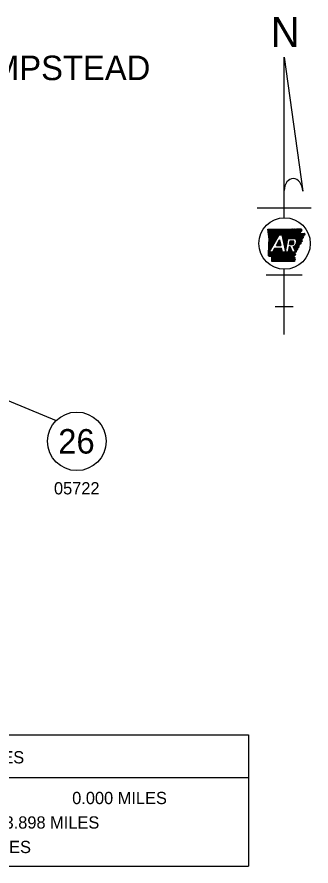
# Model space of a CAD drawing. Extents: x -12863 to 18921, y -8840 to 11152.
# Drawn here: x 4137 to 7017, y -8775 to -453 of the extents above; entities that cross this region are included whole.
import ezdxf

# ---------------------------------------------------------------- set-up
doc = ezdxf.new("R2010")
doc.units = 0
for name, color, linetype in [('Level 2', 7, 'Continuous'), ('Level 3', 7, 'Continuous'), ('Level 45', 7, 'Continuous'), ('Level 48', 7, 'Continuous'), ('Level 50', 7, 'Continuous')]:
    doc.layers.add(name, color=color, linetype=linetype)

msp = doc.modelspace()

# ---------------------------------------------------------------- linework, layer by layer
at = {"layer": 'Level 45'}
for p, q in [((-298.3, -7490), (6405.3, -7490)), ((6405.3, -7490), (6405.3, -8775.1)), ((-298.3, -7908.5), (6405.3, -7908.5)), ((-298.3, -8775.1), (6405.3, -8775.1))]:
    msp.add_line(p, q, dxfattribs=at)
at = {"layer": 'Level 48'}
for p, q in [((6754.1, -845.3), (6935.9, -2159.5)), ((6754.1, -2421.2), (6754.1, -845.3)), ((6490.9, -2323.8), (7017.2, -2323.8)), ((-312, -2404.6), (4520.7, -4409.4)), ((6594.4, -2534.1), (6596.6, -2531.9)), ((6595.2, -2540.3), (6603.6, -2531.9)), ((6596, -2546.5), (6610.5, -2531.9)), ((6596.7, -2552.7), (6617.5, -2531.9)), ((6597.5, -2558.9), (6624.4, -2531.9)), ((6598.3, -2565.1), (6631.4, -2531.9)), ((6599.1, -2571.3), (6638.4, -2532)), ((6599.8, -2577.5), (6645.3, -2532)), ((6600.6, -2583.7), (6652.3, -2532)), ((6601.4, -2589.8), (6659.3, -2532)), ((6602.1, -2596), (6666.2, -2532)), ((6602.9, -2602.2), (6673.2, -2532)), ((6603.7, -2608.4), (6680.1, -2532)), ((6604.5, -2614.6), (6687.1, -2532)), ((6604.7, -2684), (6756.9, -2531.8)), ((6604.9, -2676.8), (6749.9, -2531.9)), ((6605.2, -2669.6), (6742.9, -2531.9)), ((6605.2, -2620.8), (6694.1, -2532)), ((6605.4, -2662.4), (6736, -2531.9)), ((6605.6, -2655.2), (6729, -2531.9)), ((6605.9, -2648), (6722, -2531.9)), ((6606, -2627), (6701.1, -2532)), ((6606.1, -2640.8), (6715, -2531.9)), ((6606.4, -2633.6), (6708, -2531.9)), ((6708.1, -2587.6), (6763.9, -2531.8)), ((6715.1, -2587.6), (6770.9, -2531.8)), ((6722.1, -2587.6), (6777.9, -2531.8)), ((6729, -2587.6), (6785, -2531.6)), ((6733.4, -2590.2), (6792, -2531.5)), ((6734.6, -2595.9), (6799.1, -2531.4)), ((6735.8, -2601.7), (6806.2, -2531.3)), ((6737.1, -2607.4), (6813.3, -2531.2)), ((6738.3, -2613.2), (6820.3, -2531.1)), ((6739.5, -2618.9), (6827.4, -2531)), ((6740.7, -2624.6), (6834.5, -2530.9)), ((6742, -2630.4), (6841.6, -2530.8)), ((6743.2, -2636.1), (6848.6, -2530.7)), ((6744.4, -2641.8), (6855.7, -2530.5)), ((6745.6, -2647.6), (6862.8, -2530.4)), ((6746.9, -2653.3), (6869.9, -2530.3)), ((6748.1, -2659.1), (6877, -2530.2)), ((6749.3, -2664.8), (6884.1, -2530)), ((6797.7, -2623.4), (6891.2, -2529.9)), ((6804.7, -2623.4), (6898.4, -2529.7)), ((6811.7, -2623.4), (6905.5, -2529.5)), ((6818.6, -2623.4), (6912.6, -2529.4)), ((6825.6, -2623.4), (6919.8, -2529.2)), ((6832.5, -2623.4), (6921.3, -2534.6)), ((6839.5, -2623.4), (6924.7, -2538.2)), ((6846.5, -2623.4), (6925.6, -2544.3)), ((6853.4, -2623.4), (6909.7, -2567.1)), ((6859.8, -2624), (6908.3, -2575.5)), ((6863.6, -2627.2), (6915.6, -2575.1)), ((6867, -2630.7), (6923, -2574.7)), ((6870, -2634.7), (6930.3, -2574.4)), ((6872.6, -2639.1), (6937.7, -2574)), ((6874.7, -2643.9), (6945, -2573.6)), ((6876.3, -2649.3), (6951.6, -2574)), ((6877.2, -2655.3), (6954.9, -2577.7)), ((6603.5, -2720.1), (6662.1, -2661.5)), ((6603.7, -2712.9), (6671.2, -2645.4)), ((6604, -2705.7), (6680.3, -2629.4)), ((6604.2, -2698.5), (6689.4, -2613.3)), ((6604.5, -2691.3), (6698.4, -2597.3)), ((6606.8, -2759.2), (6703.9, -2587.6)), ((6678.2, -2691.8), (6710, -2635.7)), ((6678.6, -2691.8), (6714.4, -2656)), ((6685.5, -2691.8), (6715.6, -2661.8)), ((6686.9, -2676.5), (6713.1, -2650.3)), ((6696, -2660.5), (6711.9, -2644.5)), ((6703.9, -2587.6), (6732.8, -2587.6)), ((6705.1, -2644.4), (6710.7, -2638.8)), ((6750.6, -2670.5), (6790.1, -2631)), ((6751.8, -2676.3), (6788.6, -2639.4)), ((6753, -2682), (6787.1, -2647.9)), ((6754.2, -2687.7), (6785.7, -2656.3)), ((6791.4, -2623.4), (6858.9, -2623.4)), ((6806.1, -2684.2), (6842.7, -2647.6)), ((6807.5, -2675.8), (6835.8, -2647.6)), ((6809, -2667.4), (6828.8, -2647.6)), ((6810.5, -2659), (6821.9, -2647.6)), ((6811.9, -2650.5), (6814.9, -2647.6)), ((6812.4, -2647.6), (6844.1, -2647.6)), ((6813.1, -2684.2), (6846.6, -2650.7)), ((6820, -2684.2), (6849, -2655.3)), ((6827, -2684.2), (6850.3, -2661)), ((6847.1, -2713.3), (6924.3, -2636.1)), ((6849, -2718.4), (6925.6, -2641.8)), ((6850.8, -2723.5), (6926.9, -2647.4)), ((6852.7, -2728.6), (6928.2, -2653.1)), ((6869.8, -2683.7), (6923, -2630.4)), ((6875.8, -2670.6), (6939.1, -2607.4)), ((6877.3, -2662.2), (6938.3, -2601.3)), ((6931.3, -2622.2), (6939.9, -2613.6)), ((6951.8, -2587.7), (6958.1, -2581.4)), ((6602.3, -2756.1), (6616.6, -2741.8)), ((6602.5, -2748.9), (6625.7, -2725.7)), ((6602.8, -2741.7), (6634.8, -2709.7)), ((6603, -2734.5), (6643.9, -2693.6)), ((6603.3, -2727.3), (6653, -2677.6)), ((6603.8, -2796.4), (6677, -2723.2)), ((6608, -2799.2), (6684, -2723.2)), ((6613, -2801.2), (6691, -2723.2)), ((6621.2, -2799.9), (6697.9, -2723.2)), ((6628.3, -2799.8), (6704.9, -2723.2)), ((6633.8, -2801.3), (6711.9, -2723.2)), ((6634, -2814.9), (6725.8, -2723.2)), ((6634, -2808), (6718.8, -2723.2)), ((6634, -2821.9), (6729.4, -2726.5)), ((6634, -2828.8), (6730.7, -2732.2)), ((6634.1, -2835.8), (6731.9, -2737.9)), ((6634.1, -2842.7), (6733.1, -2743.7)), ((6660.5, -2723.2), (6640.1, -2759.2)), ((6648, -2745.2), (6670.1, -2723.2)), ((6657.1, -2729.2), (6663.1, -2723.2)), ((6728.7, -2723.2), (6660.5, -2723.2)), ((6678.2, -2691.8), (6722, -2691.8)), ((6692.5, -2691.8), (6716.8, -2667.5)), ((6699.5, -2691.8), (6718.1, -2673.2)), ((6703.7, -2849.7), (6823.5, -2729.9)), ((6706.4, -2691.8), (6719.3, -2679)), ((6710.7, -2849.7), (6825.4, -2735)), ((6713.4, -2691.8), (6720.5, -2684.7)), ((6717.6, -2849.7), (6827.3, -2740.1)), ((6720.4, -2691.8), (6721.7, -2690.5)), ((6724.6, -2849.7), (6829.2, -2745.1)), ((6755.5, -2693.5), (6784.2, -2664.7)), ((6756.7, -2699.2), (6782.7, -2673.2)), ((6757.9, -2705), (6781.3, -2681.6)), ((6759.2, -2710.7), (6779.8, -2690.1)), ((6760.4, -2716.4), (6778.3, -2698.5)), ((6761.6, -2722.2), (6776.9, -2706.9)), ((6762.8, -2727.9), (6775.4, -2715.4)), ((6764.1, -2733.6), (6773.9, -2723.8)), ((6765.3, -2739.4), (6772.4, -2732.2)), ((6766.5, -2745.1), (6771, -2740.7)), ((6794.2, -2752.3), (6821.7, -2724.8)), ((6795.7, -2743.8), (6819.8, -2719.7)), ((6797.1, -2735.4), (6817.9, -2714.6)), ((6798.6, -2727), (6816, -2709.5)), ((6800.1, -2718.5), (6814, -2704.6)), ((6801.6, -2710.1), (6807, -2704.6)), ((6814.2, -2704.6), (6802.5, -2704.6)), ((6806.1, -2684.2), (6835, -2684.2)), ((6834.4, -2759.2), (6814.2, -2704.6)), ((6834, -2684.2), (6849.7, -2668.5)), ((6842.8, -2701.7), (6864, -2759.2)), ((6843.3, -2703.2), (6845.4, -2701)), ((6845.2, -2708.2), (6858.5, -2695)), ((6854.6, -2733.7), (6896.4, -2691.9)), ((6856.5, -2738.8), (6895.6, -2699.6)), ((6858.3, -2743.8), (6894.8, -2707.4)), ((6860.2, -2748.9), (6881.6, -2727.6)), ((6862.1, -2754), (6878.6, -2737.5)), ((6904.4, -2683.9), (6914.2, -2674.1)), ((6601.2, -2792), (6634, -2759.2)), ((6601.3, -2784.9), (6627.1, -2759.2)), ((6601.6, -2777.7), (6620.1, -2759.2)), ((6601.8, -2770.5), (6613.2, -2759.2)), ((6602.1, -2763.3), (6607.5, -2757.8)), ((6640.1, -2759.2), (6606.8, -2759.2)), ((6634.2, -2849.6), (6734.4, -2749.4)), ((6641.2, -2849.6), (6735.6, -2755.2)), ((6648.1, -2849.6), (6738.5, -2759.2)), ((6655.1, -2849.6), (6745.5, -2759.2)), ((6662, -2849.6), (6752.5, -2759.2)), ((6669, -2849.6), (6759.4, -2759.2)), ((6675.9, -2849.6), (6766.4, -2759.2)), ((6682.9, -2849.7), (6773.4, -2759.2)), ((6689.8, -2849.7), (6780.3, -2759.2)), ((6696.8, -2849.7), (6787.3, -2759.2)), ((6731.6, -2849.7), (6831.1, -2750.2)), ((6793, -2759.2), (6736.4, -2759.2)), ((6738.5, -2849.8), (6832.9, -2755.3)), ((6745.5, -2849.8), (6836.1, -2759.2)), ((6752.4, -2849.8), (6843, -2759.2)), ((6759.4, -2849.8), (6850, -2759.2)), ((6766.3, -2849.8), (6857, -2759.2)), ((6767.7, -2750.9), (6769.5, -2749.1)), ((6773.3, -2849.8), (6859.3, -2763.8)), ((6780.2, -2849.8), (6859.6, -2770.5)), ((6787.2, -2849.8), (6859.9, -2777.1)), ((6794.1, -2849.8), (6860.2, -2783.8)), ((6801.1, -2849.9), (6848.8, -2802.2)), ((6808.1, -2849.9), (6850.9, -2807)), ((6815, -2849.9), (6853.1, -2811.8)), ((6822, -2849.9), (6855.2, -2816.6)), ((6828.9, -2849.9), (6857.4, -2821.4)), ((6864, -2759.2), (6834.4, -2759.2)), ((6835.9, -2849.9), (6859.2, -2826.6)), ((6842.8, -2849.9), (6856, -2836.7)), ((6849.8, -2849.9), (6852.9, -2846.8)), ((6578.6, -2979.7), (6929.5, -2979.7)), ((6754.1, -3564.9), (6754.1, -2925.3)), ((6666.3, -3291.3), (6841.8, -3291.3))]:
    msp.add_line(p, q, dxfattribs=at)
for points in [[(6594.1, -2532), (6690.2, -2532), (6774.6, -2531.8), (6874.1, -2530.3), (6920.2, -2529.2)], [(6604.8, -2681.3), (6606.5, -2630.7), (6594.1, -2532)], [(6594.2, -2531.9), (6690.3, -2532), (6774.6, -2531.8), (6874.1, -2530.3), (6920.2, -2529.2)], [(6601.1, -2791.9), (6606.5, -2630.7), (6594.2, -2531.9)], [(6950.4, -2573.3), (6958.7, -2582), (6938, -2599.1), (6940.2, -2616.3), (6922.4, -2628), (6928.5, -2654.5), (6914.8, -2667), (6913.6, -2680.6), (6896.9, -2686.6), (6894.3, -2712.2), (6882.3, -2725), (6876.6, -2744.4), (6859.1, -2760.3), (6860.4, -2788.5), (6848.6, -2801.8), (6859.4, -2825.9), (6851.9, -2849.9)], [(6905.9, -2575.6), (6951, -2573.3)], [(6905.9, -2575.6), (6951, -2573.3)], [(6710, -2635.7), (6722, -2691.8)], [(6732.8, -2587.6), (6768.5, -2754.6), (6791.4, -2623.4)], [(6806.1, -2684.2), (6812.4, -2647.6)], [(6601.1, -2791.9), (6604.8, -2681.3)], [(6736.4, -2759.2), (6728.7, -2723.2)], [(6802.5, -2704.6), (6793, -2759.2)], [(6851.9, -2850), (6634.1, -2849.6), (6634, -2801.5)], [(6851.9, -2849.9), (6634.1, -2849.6), (6634, -2801.5)]]:
    msp.add_lwpolyline(points, dxfattribs=at)
msp.add_circle((4723.6, -4612.3), 286.9, dxfattribs=at)
for centre, major_axis, ratio, start_param, end_param in [((6844.9, -2162.3), (-3.9, 126.3), 0.719778, 4.712385, 7.768526), ((6828.1, -2663), (-22.3, 0), 0.999987, 1.887169, 3.90762), ((6833.8, -2659), (-43.6, 0), 0.999987, 1.777838, 4.099264)]:
    msp.add_ellipse(centre, major_axis=major_axis, ratio=ratio, start_param=start_param, end_param=end_param, dxfattribs=at)
msp.add_ellipse((6758.2, -2673.3), major_axis=(252.1, 0), ratio=0.999976, dxfattribs=at)
for points in [[(6920.2, -2529.2), (6920.5, -2531.8), (6921.3, -2533.2), (6921.4, -2535.7), (6922.5, -2536.8), (6924.2, -2537.8), (6925.7, -2539.5), (6926.1, -2541.5), (6925.6, -2543.6), (6925.5, -2546), (6925.3, -2548), (6924.9, -2549.8), (6923.5, -2551.3), (6922.1, -2552.4), (6920.9, -2553.6), (6920, -2554.9), (6918.4, -2556.3), (6916.9, -2557.9), (6915.6, -2559.1), (6914.4, -2560.8), (6913.8, -2562.6), (6912.4, -2564), (6911.3, -2565.2), (6909.9, -2566.8), (6909.2, -2568.3), (6907.9, -2570.2), (6907.5, -2572), (6906.7, -2573.4), (6906.6, -2573.6)], [(6920.2, -2529.2), (6920.5, -2531.8), (6921.3, -2533.2), (6921.4, -2535.7), (6922.5, -2536.7), (6924.2, -2537.8), (6925.7, -2539.5), (6926.1, -2541.6), (6925.6, -2543.6), (6925.5, -2546), (6925.2, -2548), (6924.9, -2549.8), (6923.5, -2551.3), (6922.1, -2552.4), (6920.9, -2553.6), (6920, -2554.9), (6918.4, -2556.4), (6916.9, -2557.8), (6915.6, -2559.1), (6914.4, -2560.8), (6913.8, -2562.7), (6912.4, -2564), (6911.3, -2565.1), (6909.9, -2566.8), (6909.2, -2568.4), (6907.8, -2570.2), (6907.5, -2572), (6906.6, -2573.4), (6906.6, -2573.6)], [(6950.4, -2573.3), (6951, -2573.3), (6953, -2575.4), (6953.9, -2577.2), (6955.3, -2578.2), (6956.8, -2578.7), (6957.9, -2580.1), (6958.6, -2581.6), (6958.2, -2582.9), (6956.5, -2583), (6954.7, -2583.3), (6952.9, -2583.3), (6951.5, -2584.5), (6952.8, -2586.1), (6954.5, -2587.6), (6955, -2589.2), (6954.1, -2590.7), (6952.2, -2591.5), (6950.3, -2592.3), (6948.7, -2593.7), (6947.9, -2595.1), (6946, -2595.6), (6944.1, -2596.2), (6942.5, -2596.3), (6940.6, -2596.7), (6938.8, -2597.6), (6938, -2599.1), (6938.2, -2601.3), (6938.2, -2603.7), (6940.1, -2604.4), (6941.8, -2604.5), (6943.5, -2605.4), (6943.3, -2606.7), (6942.1, -2608.4), (6940.6, -2609.7), (6939.1, -2610.3), (6937.7, -2611.6), (6938.2, -2612.8), (6939.4, -2613.6), (6940.3, -2615), (6940.2, -2616.2), (6938.8, -2617.1), (6937.2, -2616.8), (6936.1, -2615.3), (6934.8, -2614.9), (6933.7, -2614.3), (6932.4, -2615.1), (6932.4, -2616.8), (6931.9, -2618.6), (6932.3, -2620), (6932.8, -2621.9), (6932.8, -2623.3), (6932.3, -2625.4), (6931.3, -2627.5), (6930.2, -2628.1), (6929.6, -2625.8), (6929.4, -2624), (6928.7, -2622.9), (6927.7, -2622.9), (6926.5, -2623.7), (6925.1, -2625.1), (6923.4, -2626.6), (6922.4, -2628.1), (6922.9, -2629.9), (6924.2, -2630.4), (6925.3, -2630.1), (6925.8, -2628.9), (6926.7, -2628.7), (6927.7, -2630.5)], [(6927.7, -2630.5), (6928, -2632.2), (6927, -2634.1), (6926.6, -2635.9), (6926.7, -2637.8), (6924.9, -2638.8), (6923.2, -2640), (6924.2, -2641.4), (6926, -2642.7), (6927.7, -2643.7), (6928.8, -2644.7), (6929.1, -2647.1), (6929.5, -2648.7), (6930.1, -2650.9), (6930.3, -2652.3), (6929.2, -2654.1), (6928, -2654.5), (6926.6, -2654.1), (6925.1, -2653.9), (6923.9, -2655.1), (6923, -2656.8), (6922.1, -2658.5), (6921.4, -2659.9), (6920.8, -2661.4), (6919.5, -2663.2), (6917.9, -2663.5), (6916, -2664), (6914.8, -2665.3), (6915, -2667.5), (6916.1, -2669), (6916.9, -2670.8), (6917.5, -2672.4), (6917.2, -2674.4), (6916.4, -2675.9), (6915.3, -2676.8), (6914.8, -2678.7), (6914.1, -2680.2), (6913.4, -2680.6), (6911.9, -2680.5), (6910.4, -2680.2), (6909.1, -2680.3), (6907.9, -2681), (6906.6, -2680.6), (6905.3, -2679.1), (6904.2, -2678.1), (6903, -2677.7), (6901.8, -2678.3), (6901.6, -2680.3), (6902.2, -2682.3), (6902.7, -2685), (6902.2, -2686.7), (6901.9, -2689.4)], [(6869, -2745.7), (6868.8, -2745.8), (6867.8, -2747.1), (6868.4, -2749.2), (6870.7, -2750), (6871.8, -2752), (6871.8, -2753.8), (6871.1, -2756.3), (6870, -2757.4), (6867.9, -2757.9), (6866.3, -2758.2), (6866.1, -2760.9), (6865.3, -2762.3), (6864.1, -2762.7), (6862.3, -2761.8), (6861.2, -2761.3), (6859.9, -2760.8), (6858.3, -2759.8), (6857, -2760), (6857.4, -2762.6), (6857.5, -2762.7), (6858.9, -2764.6), (6860.3, -2766.2), (6861, -2768)], [(6869, -2745.7), (6868.8, -2745.8), (6867.8, -2747.1), (6868.4, -2749.2), (6870.7, -2750), (6871.8, -2752), (6871.8, -2753.8), (6871.1, -2756.3), (6870, -2757.4), (6867.9, -2757.9), (6866.3, -2758.2), (6866.1, -2760.9), (6865.3, -2762.3), (6864.1, -2762.7), (6862.3, -2761.8), (6861.2, -2761.3), (6859.9, -2760.8), (6858.3, -2759.8), (6857, -2760), (6857.4, -2762.6), (6857.5, -2762.7), (6858.9, -2764.6), (6860.3, -2766.2), (6861, -2768)], [(6901.9, -2689.4), (6899.9, -2691), (6898.9, -2692.6), (6893.7, -2692.2), (6893.8, -2694), (6891.9, -2695), (6890.2, -2696.2), (6891.2, -2697.7), (6893, -2698.9), (6894.8, -2699.9), (6895.9, -2700.9), (6896.2, -2703.4), (6896.5, -2705), (6897.1, -2707.1), (6897.3, -2708.6), (6896.2, -2710.3), (6895, -2710.7), (6893.7, -2710.3), (6892.2, -2710.2), (6890.9, -2711.3), (6890, -2713), (6889.1, -2714.7), (6888.5, -2716.1), (6887.8, -2717.7), (6886.5, -2719.5), (6884.9, -2719.7), (6883, -2720.2), (6881.9, -2721.5), (6882.1, -2723.7), (6883.1, -2725.2), (6884, -2727.1), (6884.5, -2728.7), (6884.3, -2730.7), (6883.5, -2732.2), (6882.4, -2733.1), (6881.9, -2735), (6881.1, -2736.4), (6880.4, -2736.9), (6879, -2736.7), (6877.4, -2736.4), (6876.1, -2736.6), (6874.9, -2737.2), (6873.6, -2736.8), (6872.3, -2735.4), (6871.2, -2734.3), (6870, -2733.9), (6868.8, -2734.5), (6868.6, -2736.5), (6869.2, -2738.5), (6869.7, -2741.3), (6869.2, -2742.9), (6869, -2745.7)], [(6634, -2801.5), (6634.2, -2801.6), (6633.1, -2800.8), (6631.5, -2800.1), (6629.8, -2800), (6627.6, -2799.7), (6625.8, -2799.5), (6623.9, -2798.2), (6621.9, -2799.5), (6619.6, -2800.5), (6618.3, -2799.4), (6616.6, -2800.1), (6615.4, -2799.7), (6613.3, -2801.2), (6611.3, -2800.7), (6609.9, -2801.1), (6608.1, -2801), (6607.8, -2799), (6606, -2798.7), (6604.5, -2797.9), (6603.6, -2795.8), (6602.8, -2794.2), (6601.1, -2791.9)], [(6634, -2801.5), (6634.2, -2801.6), (6633.1, -2800.8), (6631.5, -2800.1), (6629.8, -2800), (6627.6, -2799.7), (6625.8, -2799.5), (6623.9, -2798.2), (6621.9, -2799.5), (6619.6, -2800.5), (6618.3, -2799.4), (6616.6, -2800.1), (6615.4, -2799.8), (6613.3, -2801.2), (6611.3, -2800.7), (6609.9, -2801.1), (6608.1, -2801), (6607.8, -2799), (6606, -2798.7), (6604.6, -2797.9), (6603.5, -2795.8), (6602.8, -2794.2), (6601.1, -2791.9)], [(6861, -2768), (6860.4, -2769.4), (6859.7, -2771.8), (6859.9, -2773.8), (6860.8, -2775.5), (6862.2, -2776.5), (6863.8, -2777.8), (6863.7, -2779.9), (6862.8, -2780.7), (6860.7, -2780.2), (6859.1, -2779.4), (6857.7, -2779.9), (6855.9, -2780.7), (6854.5, -2781), (6854.6, -2783.8), (6856.4, -2785.8), (6858, -2785.8), (6859.9, -2786), (6860.5, -2788.2), (6859.4, -2790), (6857.7, -2790.9), (6855.4, -2789.8), (6853.8, -2788.7), (6852.2, -2787.6), (6850.2, -2787.1), (6849, -2787.3), (6848.5, -2789.8), (6849.5, -2792), (6851, -2793.6), (6852.4, -2795.6), (6852.2, -2797.1), (6851.1, -2797.5), (6849.2, -2797.9), (6848.1, -2798.5), (6847.8, -2799), (6848.4, -2801), (6848.9, -2803.2), (6848.9, -2804.9), (6848.3, -2806.4), (6847.3, -2808.8), (6847.4, -2810.3), (6848.1, -2811.1), (6849, -2810.8), (6850.2, -2810), (6851, -2809), (6851.6, -2807.8), (6852.8, -2806.9), (6854.4, -2807.7), (6854.8, -2809.6), (6853.9, -2811.2), (6852.6, -2811.9), (6851.1, -2812.5), (6849.9, -2813.8), (6850.2, -2815.4), (6851.1, -2816.2), (6853.4, -2815.8), (6854.8, -2815.1), (6855.7, -2814.3), (6856.7, -2813.3), (6857.2, -2812.2), (6858, -2811.2), (6859.4, -2810.9), (6860, -2811.8), (6859.7, -2813.8), (6858.9, -2815.7), (6857.8, -2817.3), (6856.5, -2818.4), (6855, -2820.9), (6855.3, -2823.1), (6855.9, -2825), (6856.7, -2826.4), (6858.1, -2826.1), (6859.7, -2825.9), (6860.7, -2826.7), (6860.6, -2828.4), (6859.4, -2830), (6858.3, -2831.5), (6857.7, -2833.6), (6857.9, -2835.2), (6857.9, -2836.5), (6857.4, -2838), (6856.6, -2838.8), (6854.4, -2838.8), (6852.1, -2838.5), (6850.9, -2839.2), (6851.1, -2841.3), (6852.4, -2842.8), (6853.4, -2843.5), (6854.8, -2845.2), (6855.3, -2846.5), (6855.2, -2847.7), (6854.3, -2848.8), (6851.9, -2850)], [(6861, -2768), (6860.4, -2769.4), (6859.7, -2771.8), (6859.9, -2773.8), (6860.8, -2775.5), (6862.2, -2776.5), (6863.8, -2777.8), (6863.7, -2779.9), (6862.8, -2780.7), (6860.7, -2780.2), (6859.1, -2779.4), (6857.7, -2779.9), (6855.9, -2780.7), (6854.5, -2781), (6854.6, -2783.8), (6856.4, -2785.8), (6858, -2785.8), (6859.9, -2786), (6860.5, -2788.2), (6859.4, -2790), (6857.7, -2790.9), (6855.4, -2789.8), (6853.8, -2788.7), (6852.2, -2787.6), (6850.2, -2787.1), (6849, -2787.3), (6848.5, -2789.8), (6849.5, -2792), (6851, -2793.6), (6852.4, -2795.6), (6852.2, -2797.1), (6851.1, -2797.5), (6849.2, -2797.9), (6848.1, -2798.5), (6847.8, -2799), (6848.4, -2801), (6848.9, -2803.2), (6848.9, -2804.9), (6848.3, -2806.4), (6847.3, -2808.8), (6847.4, -2810.3), (6848.1, -2811.1), (6849, -2810.8), (6850.2, -2810), (6851, -2809), (6851.6, -2807.8), (6852.8, -2806.9), (6854.4, -2807.7), (6854.8, -2809.6), (6853.9, -2811.2), (6852.6, -2811.9), (6851.1, -2812.5), (6849.9, -2813.8), (6850.2, -2815.4), (6851.1, -2816.2), (6853.4, -2815.8), (6854.8, -2815.1), (6855.7, -2814.3), (6856.7, -2813.3), (6857.2, -2812.2), (6858, -2811.2), (6859.4, -2810.9), (6860, -2811.8), (6859.7, -2813.8), (6858.9, -2815.7), (6857.8, -2817.3), (6856.5, -2818.4), (6855, -2820.9), (6855.3, -2823.1), (6855.9, -2825), (6856.7, -2826.4), (6858.1, -2826.1), (6859.7, -2825.9), (6860.7, -2826.7), (6860.6, -2828.4), (6859.4, -2830), (6858.3, -2831.5), (6857.7, -2833.6), (6857.9, -2835.2), (6857.9, -2836.5), (6857.4, -2838), (6856.6, -2838.8), (6854.4, -2838.8), (6852.1, -2838.5), (6850.9, -2839.2), (6851.1, -2841.3), (6852.4, -2842.8), (6853.4, -2843.5), (6854.8, -2845.2), (6855.3, -2846.5), (6855.2, -2847.7), (6854.3, -2848.8), (6851.9, -2850)]]:
    msp.add_spline(points, degree=3, dxfattribs=at)

# ---------------------------------------------------------------- texts
at = {"layer": 'Level 2'}
msp.add_text('HEMPSTEAD', height=240, dxfattribs=at).set_placement((3446.3, -1071.7))
at = {"layer": 'Level 3'}
for s, p in [('LENGTH CALCULATED ALONG C.L. BRIDGES', (738.9, -7769.1)), ('0.000 MILES', (4677.8, -8168.2)), ('20579.52 FEET   3.898 MILES', (2757.8, -8408.2)), ('NET LENGTH OF PROJECT   20579.52 FEET   3.898 MILES', (-122.2, -8648.2))]:
    msp.add_text(s, height=120, dxfattribs=at).set_placement(p)
at = {"layer": 'Level 48'}
for s, height, p in [('N', 293.3, (6623.3, -746.2)), ('STS 10-03-17', 7.288, (6734.1, -2923.3)), ('26', 240, (4541.2, -4732.3))]:
    msp.add_text(s, height=height, dxfattribs=at).set_placement(p)
at = {"layer": 'Level 50'}
msp.add_text('05722', height=120, dxfattribs=at).set_placement((4499.6, -5132.5))

doc.saveas('drawing.dxf')
